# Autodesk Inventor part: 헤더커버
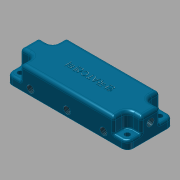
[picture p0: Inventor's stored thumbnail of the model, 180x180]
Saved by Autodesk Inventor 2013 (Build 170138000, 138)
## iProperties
Created: 2015-11
Part Number: 헤더커버
Material: 알루미늄 6061
Document SubType Name: Modeling
Designer: mduedu
Density: 2.71 g/cm^3
Mass: 171.771 g
Surface Area: 160.862 cm^2
Volume: 63.3841 cm^3
Author: mduedu
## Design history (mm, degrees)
sketch "스케치1"
  geometry: L1 (52.5, 20)-(-52.5, 20); L2 (-52.5, 20)-(-52.5, -20); L3 (-52.5, -20)-(52.5, -20); L4 (52.5, -20)-(52.5, 20); L5 (52.5, 20)-(-52.5, -20); L6 (-52.5, 20)-(52.5, -20); 1 further point
  constraints: 12 end point, 2 midpoint, 2 parallel, 1 horizontal, 1 perpendicular
  dimensions: "d0" = 105 distance of L3.end L2.end; "d1" = 40 distance of L2.end L1.end
extrude "돌출1" new body sketch "스케치1" distance "d2" = 20; taper "d3" = 0 deg
sketch "스케치2"
  geometry: L1 (-52.5, -20)-(-52.5, 20) reference; L2 (-52.5, 20)-(52.5, 20) reference; L3 (52.5, 20)-(52.5, -20) reference; L4 (52.5, -20)-(-52.5, -20) reference; L5 (-52.5, 20)-(-40.5, 20); L6 (-40.5, 20)-(-40.5, 8); L7 (-40.5, 8)-(-52.5, 8); L8 (-52.5, 8)-(-52.5, 20); L9 (52.5, 20)-(40.5, 20); L10 (40.5, 20)-(40.5, 8); L11 (40.5, 8)-(52.5, 8); L12 (52.5, 8)-(52.5, 20); L13 (52.5, -20)-(40.5, -20); L14 (40.5, -20)-(40.5, -8); L15 (40.5, -8)-(52.5, -8); L16 (52.5, -8)-(52.5, -20); L17 (-52.5, -20)-(-40.5, -20); L18 (-40.5, -20)-(-40.5, -8); L19 (-40.5, -8)-(-52.5, -8); L20 (-52.5, -8)-(-52.5, -20); 1 further point
  constraints: 32 end point, 8 parallel, 6 equal length, 4 horizontal, 4 perpendicular
  dimensions: "d4" = 12 distance of L6.end L7.end; "d5" = 12 distance of L5.end L6.end
extrude "돌출2" cut sketch "스케치2" distance "d6" = 13; taper "d7" = 0 deg
fillet "모깎기1" dims "d8" = 5
fillet "모깎기2" dims "d9" = 1
fillet "모깎기3" dims "d10" = 5
fillet "모깎기4" dims "d11" = 2
fillet "모깎기5" dims "d12" = 3
sketch "스케치3"
  geometry: L1 (-46.5, -14)-(46.5, -14); L2 (46.5, -14)-(46.5, 14); L3 (46.5, 14)-(-46.5, 14); L4 (-46.5, 14)-(-46.5, -14); L5 (-46.5, -14)-(46.5, 14); L6 (46.5, -14)-(-46.5, 14); L7 (47.5, 20)-(-47.5, 20) reference; L8 (52.5, -15)-(52.5, 15) reference; 5 further points
  constraints: 12 end point, 4 coincident, 2 midpoint, 2 parallel, 1 horizontal, 1 perpendicular
  dimensions: "d13" = 6 distance between parallel lines of L3 L7; "d14" = 6 distance between parallel lines of L2 L8
hole "구멍1" sketch "스케치3" at (-46.5, 14), (46.5, 14), (46.5, -14), (-46.5, -14) diameter "d15" = 4.5; stored, may be unused: countersink angle "d19" = 90 deg, drill point angle "d21" = 118 deg; dims "d16" = 6, "d17" = 4, "d18" = 2, "d20" = 8
sketch "스케치4"
  geometry: L1 (47.5, -20)-(-47.5, -20) reference; L2 (52.5, 15)-(52.5, -15) reference; L3 (-47.5, 20)-(47.5, 20) reference; L4 (-52.5, -15)-(-52.5, 15) reference; L5 (-52.5, 0)-(52.5, 0); C1 r 12.25 at (0, 0); C2 r 2.25 at (46.5, 14) reference; C3 r 2.25 at (-46.5, -14) reference; C4 r 2.25 at (46.5, -14) reference; C5 r 2.25 at (-46.5, 14) reference; C6 r 12.25 at (-32, 0); C7 r 12.25 at (32, 0); A1 r 5 centre (-47.5, -15) between (-52.5, -15) and (-47.5, -20) reference; A2 r 5 centre (47.5, -15) between (47.5, -20) and (52.5, -15) reference; A3 r 5 centre (47.5, 15) between (52.5, 15) and (47.5, 20) reference; A4 r 5 centre (-47.5, 15) between (-47.5, 20) and (-52.5, 15) reference; 1 further point
  constraints: 3 centre point, 2 end point, 2 midpoint, 2 point on line, 1 coincident
  dimensions: "d22" = 24.5 diameter of C1; "d23" = 24.5 diameter of C7 (= d22); "d24" = 24.5 diameter of C6 (= d22); "d25" = 32 distance of point (0, 0) C6.centre; "d26" = 32 distance of C7.centre point (0, 0) (= d25)
extrude "돌출3" cut sketch "스케치4" distance "d27" = 8; taper "d28" = 0 deg
fillet "모깎기6" dims "d29" = 5
sketch "스케치5"
  geometry: L1 (-52.5, 12)-(-47.119, 12); L2 (-40.191, 8)-(-37.635, 3.574); L3 (-52.5, 17)-(-52.5, 8) reference; L4 (-47.5, 0)-(-52.5, 0) reference; L5 (37.5, 20)-(-37.5, 20) reference; L6 (0, 0)-(0, 20); L7 (52.5, 12)-(47.119, 12); L8 (40.191, 8)-(37.635, 3.574); A1 r 8 centre (-47.119, 4) between (-40.191, 8) and (-47.119, 12); A2 r 8 centre (47.119, 4) between (47.119, 12) and (40.191, 8); 1 further point
  constraints: 10 end point, 5 symmetric about line, 4 point on circle, 3 point on line, 2 centre point, 2 tangent, 1 horizontal, 1 midpoint, 1 other
  dimensions: "d30" = 10 distance of L1.start point (-42.5, 12); "d32" = 120 deg angle of L2 L1; "d34" = 12 distance between parallel lines of L1 L4; "d35" = 8 radius of A1
sketch "스케치6"
  geometry: L1 (20, -5)-(20, 5) reference; L2 (8, -20)-(17, -20) reference; L3 (12, -20)-(12, -14.619); L4 (8, -7.691)-(3.81, -5.272); L5 (0, -20)-(0, -15) reference; A1 r 8 centre (4, -14.619) between (12, -14.619) and (8, -7.691); 2 further points
  constraints: 4 end point, 3 point on line, 2 point on circle, 2 tangent, 1 centre point, 1 perpendicular
  dimensions: "d36" = 10 distance of L3.start point (12, -10); "d38" = 12 distance between parallel lines of L3 L5; "d39" = 120 deg angle of L3 L4; "d40" = 8 radius of A1
node "작업점1"
node "작업점2"
node "작업점3"
hole "구멍2" diameter "d43" = 5.944; stored, may be unused: countersink angle "d49" = 90 deg, drill point angle "d51" = 0 deg; dims "d41" = 10, "d42" = 10, "d44" = 6.886, "d45" = 0.62479, "d46" = 5.959, "d47" = 4, "d48" = 2, "d50" = 6.9
hole "구멍3" diameter "d54" = 5.944; stored, may be unused: countersink angle "d60" = 90 deg, drill point angle "d62" = 0 deg; dims "d52" = 10, "d53" = 10, "d55" = 6.886, "d56" = 0.62479, "d57" = 5.959, "d58" = 4, "d59" = 2, "d61" = 6.9
hole "구멍4" diameter "d65" = 5.944; stored, may be unused: countersink angle "d71" = 90 deg, drill point angle "d73" = 0 deg; dims "d63" = 10, "d64" = 10, "d66" = 6.886, "d67" = 0.62479, "d68" = 5.959, "d69" = 4, "d70" = 2, "d72" = 6.9
sketch "스케치7"
  geometry: C1 r 2.972 at (15, 12) reference; 1 further point
sketch "스케치8"
  geometry: C1 r 2.972 at (15, 12) reference; 1 further point
sketch "스케치9"
  geometry: C1 r 2.972 at (47.5, 12) reference; 1 further point
feature "스윕1" dims "d74" = 0
feature "스윕2" dims "d75" = 0
feature "스윕3" dims "d76" = 0
sketch "스케치10"
  geometry: L1 (0, 0)-(95, 0) reference; L2 (22.75, 8)-(8.768, 8) reference; L3 (54.75, 8)-(40.25, 8) reference; L4 (86.232, 8)-(72.25, 8) reference; L5 (15.759, 8)-(15.759, 0); L6 (47.5, 8)-(47.5, 0); L7 (79.241, 8)-(79.241, 0); 5 further points
  constraints: 6 end point, 5 point on line, 3 midpoint, 2 horizontal alignment, 2 perpendicular, 1 parallel
  dimensions: "d77" = 5 distance from line of point (15.759, 5) L1
hole "구멍5" sketch "스케치10" at (15.759, 5), (47.5, 5), (79.241, 5) diameter "d78" = 5.944; stored, may be unused: countersink angle "d84" = 90 deg, drill point angle "d86" = 0 deg; dims "d79" = 6.886, "d80" = 0.62479, "d81" = 5.959, "d82" = 4, "d83" = 2, "d85" = 6.9
sketch "스케치11"
  geometry: C1 r 2.972 at (0, 0) reference; C2 r 2.972 at (31.741, 0) reference; C3 r 2.972 at (63.482, 0) reference; 1 further point
extrude "돌출4" cut sketch "스케치11" distance "d87" = 8; taper "d88" = 0 deg
sketch "스케치12"
  geometry: 2 further points
  constraints: 1 coincident, 1 other
feature "엠보싱1" sketch "스케치12" dims "d0" = 105, "d1" = 40, "d4" = 12, "d5" = 12, "d89" = 0.5, "d90" = 0
node "솔리드1"
node "투영된 루프1"
node "절단 모서리 투영1"
